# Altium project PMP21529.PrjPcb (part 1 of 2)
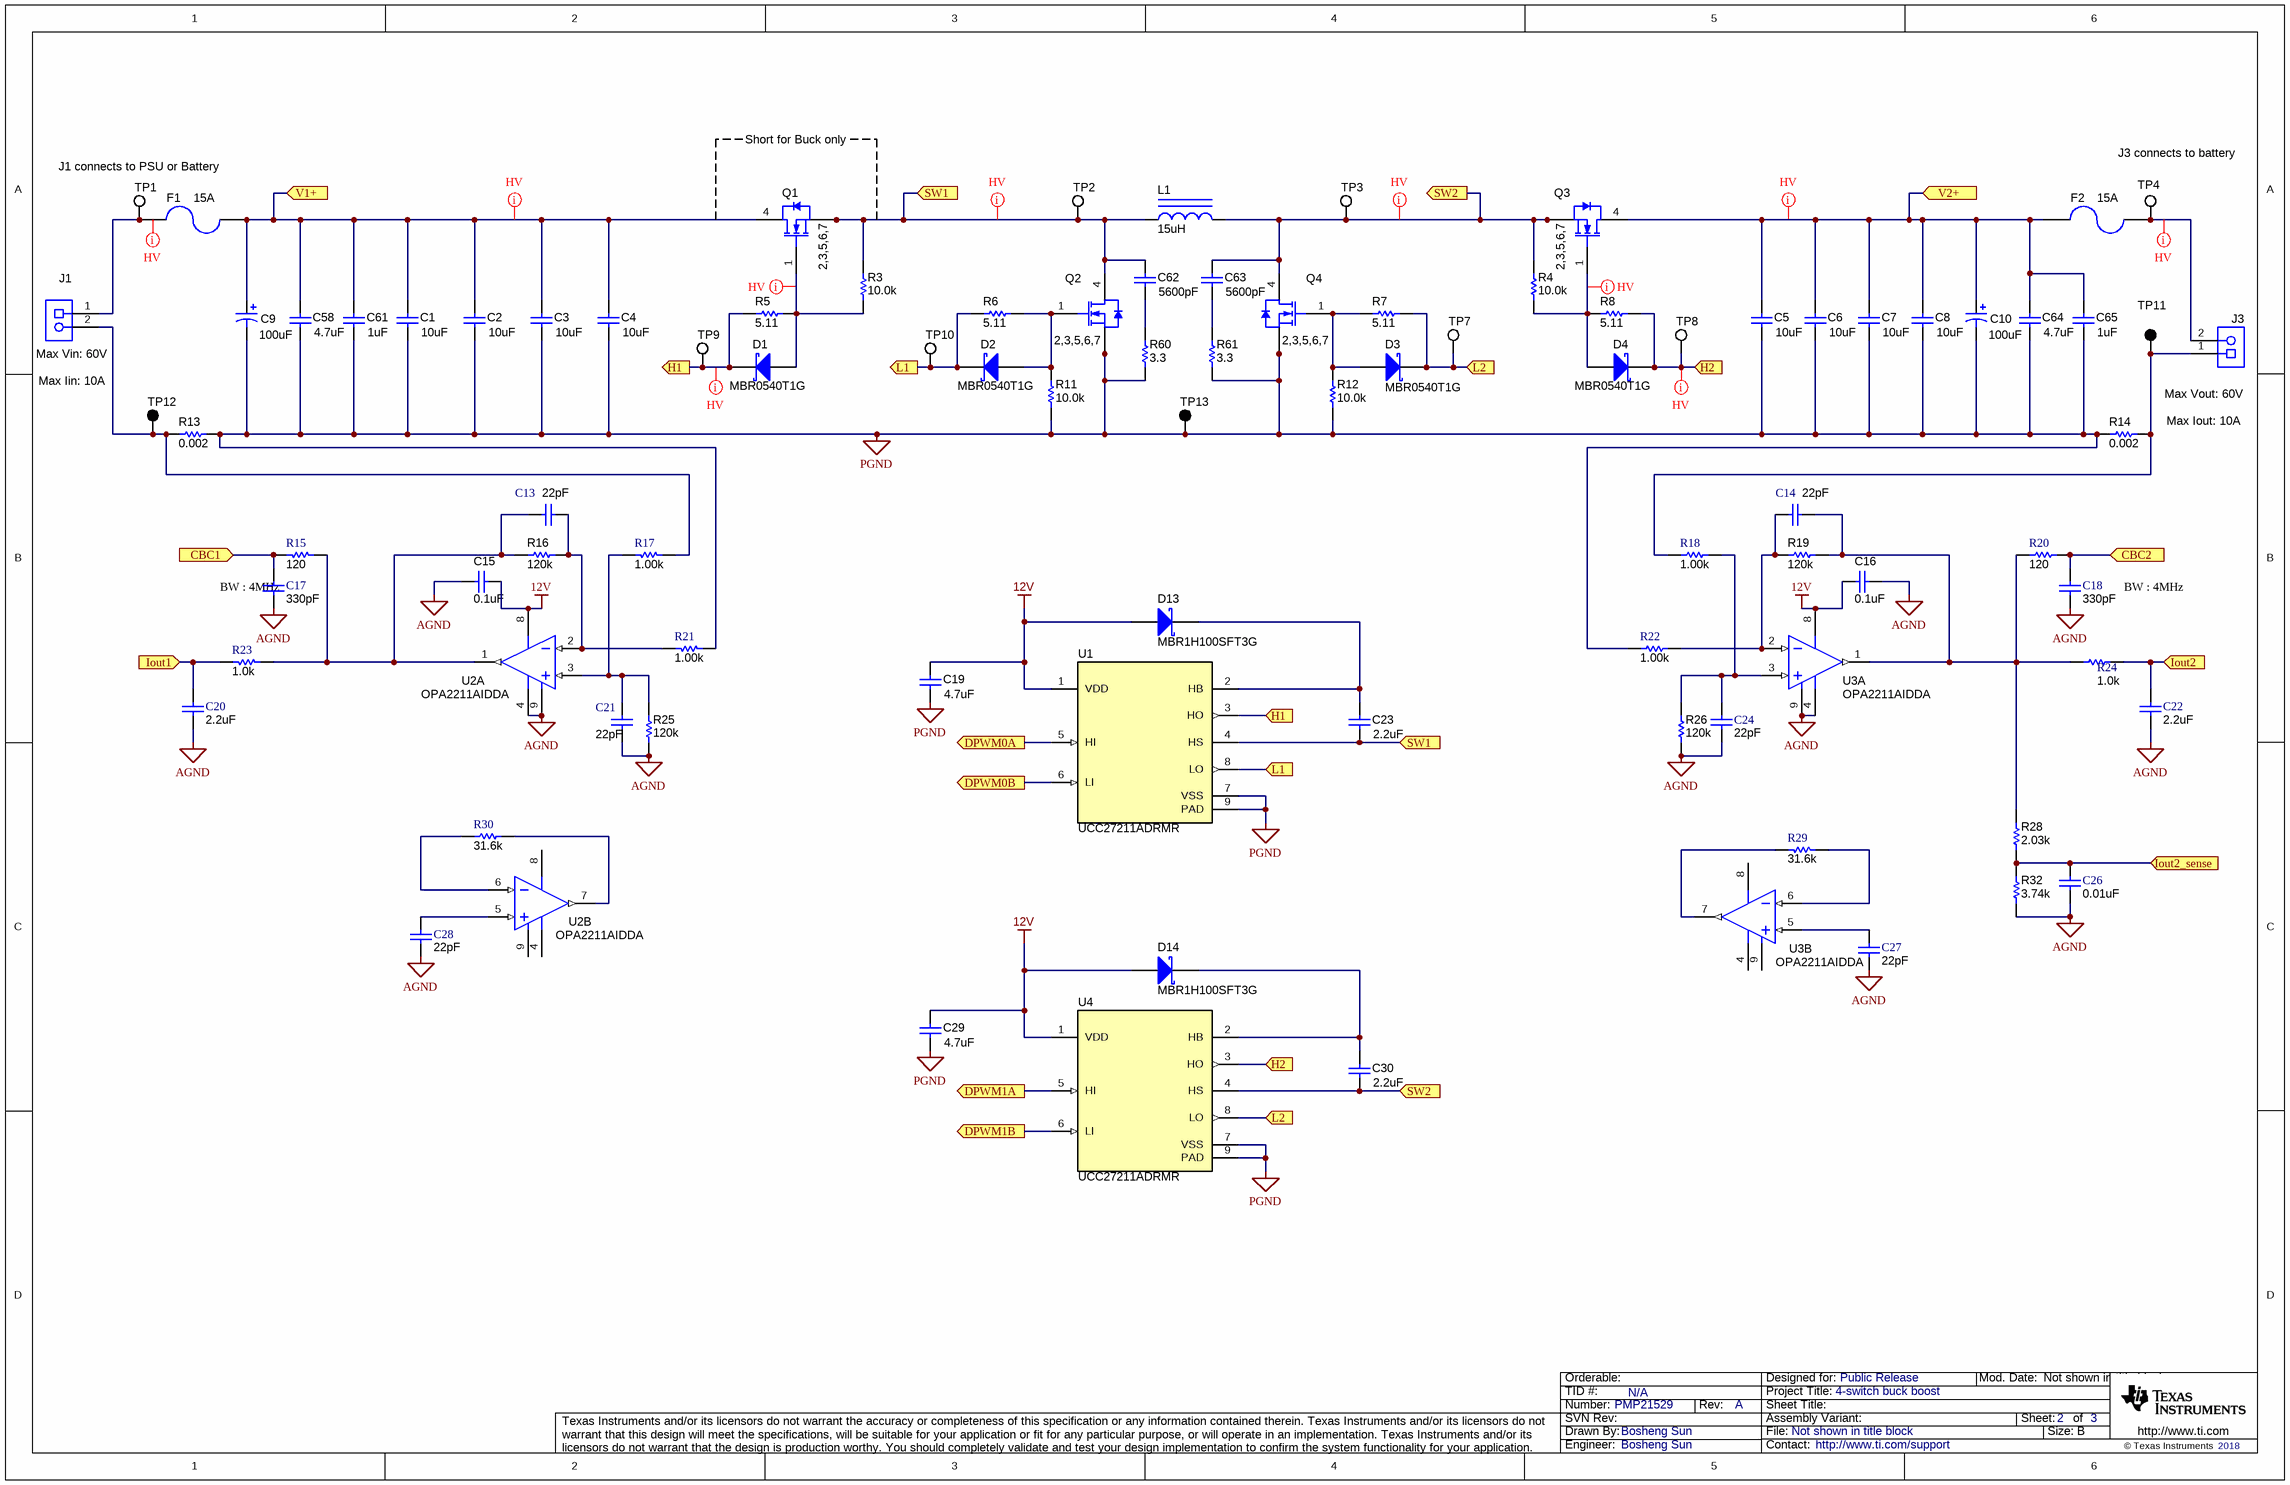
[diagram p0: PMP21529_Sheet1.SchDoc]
CopyrightYear: 2018; PCB_Layout: Bosheng Sun; PCB_Rev: A; PRJ_Customer: Public Release; PRJ_Engineer: Bosheng Sun; PRJ_Number: PMP21529; PRJ_Title: 4-switch buck boost; SCH_Rev: A; TechSupport: http://www.ti.com/support; TID: N/A
3 sheets, 197 parts. Net scope: flat (ports and power ports of the same name join across sheets).
Board file: PMP21529.PcbDoc
Sheets:
  PMP21529_Sheet1.SchDoc
  PMP21529_Sheet2.SchDoc
  PMP21529_Hardware.SchDoc

## Sheet PMP21529_Sheet1.SchDoc
size 431 x 279 mm; Date: Not shown in title block; ApprovedBy: Not shown in title block; CheckedBy: Not shown in title block; Author: Not shown in title block; CompanyName: Not shown in title block; DrawnBy: Bosheng Sun; Engineer: Not shown in title block; Organization: Not shown in title block; Address1: Not shown in title block; Address2: Not shown in title block; Address3: Not shown in title block; Address4: Not shown in title block; DocumentNumber: 1; Revision: Use project parameter SCH_Rev; SheetNumber: 2; SheetTotal: 3; PageSetup: Record=PageOptions¦CenterHorizontal=True¦CenterVertical=True¦PrintScale=1.00¦XCorrection=1.00¦YCorrection=1.00¦PrintKind=0¦BorderSize=5000000¦LeftOffset=0¦BottomOffset=0¦Orientation=2¦PaperLength=1000¦PaperWidth=1000¦Scale=100¦PaperSource=15¦PrintQuality=600¦MediaType=1¦DitherType=10¦PaperKind=Letter¦PrintScaleMode=1

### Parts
C1  ValueDisplayed: 10uF  [2220_280]  (hidden comment: 22201C106MAT2A)
C2  ValueDisplayed: 10uF  [2220_280]  (hidden comment: 22201C106MAT2A)
C3  ValueDisplayed: 10uF  [2220_280]  (hidden comment: 22201C106MAT2A)
C4  ValueDisplayed: 10uF  [2220_280]  (hidden comment: 22201C106MAT2A)
C5  ValueDisplayed: 10uF  [2220_280]  (hidden comment: 22201C106MAT2A)
C6  ValueDisplayed: 10uF  [2220_280]  (hidden comment: 22201C106MAT2A)
C7  ValueDisplayed: 10uF  [2220_280]  (hidden comment: 22201C106MAT2A)
C8  ValueDisplayed: 10uF  [2220_280]  (hidden comment: 22201C106MAT2A)
C9  ValueDisplayed: 100uF  [CAPSMT_62_KE0]  (hidden comment: EMVA101ATR101MKE0S)
C10  ValueDisplayed: 100uF  [CAPSMT_62_KE0]  (hidden comment: EMVA101ATR101MKE0S)
C13  ValueDisplayed: 22pF  [0603]  (hidden comment: Capacitor)
C14  ValueDisplayed: 22pF  [0603]  (hidden comment: Capacitor)
C15  ValueDisplayed: 0.1uF  [0603]  (hidden comment: Capacitor)
C16  ValueDisplayed: 0.1uF  [0603]  (hidden comment: Capacitor)
C17  ValueDisplayed: 330pF  [0603]  (hidden comment: Capacitor)
C18  ValueDisplayed: 330pF  [0603]  (hidden comment: Capacitor)
C19  ValueDisplayed: 4.7uF  [0805_HV]  (hidden comment: GRM21BR71C475KA73L)
C20  ValueDisplayed: 2.2uF  [0603]  (hidden comment: Capacitor)
C21  ValueDisplayed: 22pF  [0603]  (hidden comment: Capacitor)
C22  ValueDisplayed: 2.2uF  [0603]  (hidden comment: Capacitor)
C23  ValueDisplayed: 2.2uF  [1206_180]  (hidden comment: C3216X7S2A225K160AB)
C24  ValueDisplayed: 22pF  [0603]  (hidden comment: Capacitor)
C26  ValueDisplayed: 0.01uF  [0603]  (hidden comment: Capacitor)
C27  ValueDisplayed: 22pF  [0603]  (hidden comment: Capacitor)
C28  ValueDisplayed: 22pF  [0603]  (hidden comment: Capacitor)
C29  ValueDisplayed: 4.7uF  [0805_HV]  (hidden comment: GRM21BR71C475KA73L)
C30  ValueDisplayed: 2.2uF  [1206_180]  (hidden comment: C3216X7S2A225K160AB)
C58  ValueDisplayed: 4.7uF  [1210_220]  (hidden comment: GRM32DC72A475KE01L)
C61  ValueDisplayed: 1uF  [1206_180]  (hidden comment: C3216X7R2A105K160AA)
C62  ValueDisplayed: 5600pF  [1206]  (hidden comment: GRM3195C2A562JA01D)
C63  ValueDisplayed: 5600pF  [1206]  (hidden comment: GRM3195C2A562JA01D)
C64  ValueDisplayed: 4.7uF  [1210_220]  (hidden comment: GRM32DC72A475KE01L)
C65  ValueDisplayed: 1uF  [1206_180]  (hidden comment: C3216X7R2A105K160AA)
D1  MBR0540T1G  [SOD-123]
D2  MBR0540T1G  [SOD-123]
D3  MBR0540T1G  [SOD-123]
D4  MBR0540T1G  [SOD-123]
D13  MBR1H100SFT3G  [SOD-123FL]
D14  MBR1H100SFT3G  [SOD-123FL]
F1  Irating_A: 15A  [FUSE_SSQ]  (hidden comment: SSQ 15)
F2  Irating_A: 15A  [FUSE_SSQ]  (hidden comment: SSQ 15)
J1  Receptacle_2x1  [On-Shore_ED120_2DS]  (value not drawn)
J3  Receptacle_2x1  [On-Shore_ED120_2DS]  (value not drawn)
L1  ValueDisplayed: 15uH  [SER2918H]  (hidden comment: SER2918H-153KL)
Q1  IPB180N08S402ATMA1  [DDPAK-7]  (value not drawn)
Q2  IPB180N08S402ATMA1  [DDPAK-7]  (value not drawn)
Q3  IPB180N08S402ATMA1  [DDPAK-7]  (value not drawn)
Q4  IPB180N08S402ATMA1  [DDPAK-7]  (value not drawn)
R3  ValueDisplayed: 10.0k  [0603]  (hidden comment: CRCW060310K0FKEA)
R4  ValueDisplayed: 10.0k  [0603]  (hidden comment: CRCW060310K0FKEA)
R5  ValueDisplayed: 5.11  [0805_HV]  (hidden comment: CRCW08055R11FKEA)
R6  ValueDisplayed: 5.11  [0805_HV]  (hidden comment: CRCW08055R11FKEA)
R7  ValueDisplayed: 5.11  [0805_HV]  (hidden comment: CRCW08055R11FKEA)
R8  ValueDisplayed: 5.11  [0805_HV]  (hidden comment: CRCW08055R11FKEA)
R11  ValueDisplayed: 10.0k  [0603]  (hidden comment: CRCW060310K0FKEA)
R12  ValueDisplayed: 10.0k  [0603]  (hidden comment: CRCW060310K0FKEA)
R13  ValueDisplayed: 0.002  [2512]  (hidden comment: Resistor)
R14  ValueDisplayed: 0.002  [2512]  (hidden comment: Resistor)
R15  ValueDisplayed: 120  [0603]  (hidden comment: Resistor)
R16  ValueDisplayed: 120k  [0603]  (hidden comment: RC0603FR-07120KL)
R17  ValueDisplayed: 1.00k  [0603]  (hidden comment: Resistor)
R18  ValueDisplayed: 1.00k  [0603]  (hidden comment: Resistor)
R19  ValueDisplayed: 120k  [0603]  (hidden comment: RC0603FR-07120KL)
R20  ValueDisplayed: 120  [0603]  (hidden comment: Resistor)
R21  ValueDisplayed: 1.00k  [0603]  (hidden comment: Resistor)
R22  ValueDisplayed: 1.00k  [0603]  (hidden comment: Resistor)
R23  value 1.0k  [0603]  (hidden comment: Resistor)
R24  value 1.0k  [0603]  (hidden comment: Resistor)
R25  ValueDisplayed: 120k  [0603]  (hidden comment: RC0603FR-07120KL)
R26  ValueDisplayed: 120k  [0603]  (hidden comment: RC0603FR-07120KL)
R28  ValueDisplayed: 2.03k  [0603]  (hidden comment: RT0603DRE072K03L)
R29  value 31.6k  [0603]  (hidden comment: Resistor)
R30  value 31.6k  [0603]  (hidden comment: Resistor)
R32  ValueDisplayed: 3.74k  [0603]  (hidden comment: RC0603FR-073K74L)
R60  ValueDisplayed: 3.3  [2010]  (hidden comment: CRM2010-JW-3R3ELF)
R61  ValueDisplayed: 3.3  [2010]  (hidden comment: CRM2010-JW-3R3ELF)
TP1  5012  [Keystone5012]  (value not drawn)
TP2  5012  [Keystone5012]  (value not drawn)
TP3  5012  [Keystone5012]  (value not drawn)
TP4  5012  [Keystone5012]  (value not drawn)
TP7  5012  [Keystone5012]  (value not drawn)
TP8  5012  [Keystone5012]  (value not drawn)
TP9  5012  [Keystone5012]  (value not drawn)
TP10  5012  [Keystone5012]  (value not drawn)
TP11  5011  [Keystone5011]  (value not drawn)
TP12  5011  [Keystone5011]  (value not drawn)
TP13  5011  [Keystone5011]  (value not drawn)
U1  UCC27211ADRMR  [DRM0008A]
U2  OPA2211AIDDA  [DDA0008C_M]  (parts A,B of 2)
U3  OPA2211AIDDA  [DDA0008C_M]  (parts A,B of 2)
U4  UCC27211ADRMR  [DRM0008A]

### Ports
CBC1, CBC2, DPWM0A, DPWM0B, DPWM1A, DPWM1B, H1, H2, Iout1, Iout2, Iout2_sense, L1, L2, SW1, SW2, V1+, V2+

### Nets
12V: C15.1 C16.1 C19.1 C29.1 D13.2(A) D14.2(A) U1.1(VDD) U2.8(V+) U3.8(V+) U4.1(VDD)
AGND: C15.2 C16.2 C17.2 C18.2 C20.2 C21.2 C22.2 C24.2 C26.2 C27.2 C28.2 R25.1 R26.1 R32.1 U2.4(V-) U2.9(EP) U3.4(V-) U3.9(EP)
PGND: C1.2 C2.2 C3.2 C4.2 C5.2 C6.2 C7.2 C8.2 C9.2(-) C10.2(-) C19.2 C29.2 C58.2 C61.2 C64.2 C65.2 Q2.2(S) Q2.3(S) Q2.5(S) Q2.6(S) Q2.7(S) Q4.2(S) Q4.3(S) Q4.5(S) Q4.6(S) Q4.7(S) R11.1 R12.1 R13.2 R14.1 R21.1 R22.1 R60.1 R61.1 TP13.1 U1.7(VSS) U1.9(PAD) U4.7(VSS) U4.9(PAD)
CBC1: C17.1 R15.2 ; port CBC1
CBC2: C18.1 R20.2 ; port CBC2
DPWM0A: U1.5(HI) ; port DPWM0A
DPWM0B: U1.6(LI) ; port DPWM0B
DPWM1A: U4.5(HI) ; port DPWM1A
DPWM1B: U4.6(LI) ; port DPWM1B
H1: D1.1(K) R5.1 TP9.1 U1.3(HO) ; port H1
H2: D4.1(K) R8.2 TP8.1 U4.3(HO) ; port H2
Iout1: C20.1 R23.2 ; port Iout1
Iout2: C22.1 R24.2 ; port Iout2
Iout2_sense: C26.1 R28.1 R32.2 ; port Iout2_sense
L1: D2.1(K) R6.1 TP10.1 U1.8(LO) ; port L1
L2: D3.1(K) R7.2 TP7.1 U4.8(LO) ; port L2
SW1: C23.2 C62.1 L1.1 Q1.2(S) Q1.3(S) Q1.5(S) Q1.6(S) Q1.7(S) Q2.4(D) R3.2 TP2.1 U1.4(HS) ; port SW1
SW2: C30.2 C63.1 L1.2 Q3.2(S) Q3.3(S) Q3.5(S) Q3.6(S) Q3.7(S) Q4.4(D) R4.2 TP3.1 U4.4(HS) ; port SW2
V1+: C1.1 C2.1 C3.1 C4.1 C9.1(+) C58.1 C61.1 F1.1 Q1.4(D) ; port V1+
V2+: C5.1 C6.1 C7.1 C8.1 C10.1(+) C64.1 C65.1 F2.2 Q3.4(D) ; port V2+
NetC13_1: C13.1 R16.2 R21.2 U2.2(IN_A-)
NetC13_2: C13.2 R15.1 R16.1 R23.1 U2.1(OUT_A)
NetC14_1: C14.1 R19.1 R22.2 U3.2(IN_A-)
NetC14_2: C14.2 R19.2 R20.1 R24.1 R28.2 U3.1(OUT_A)
NetC21_1: C21.1 R17.2 R25.2 U2.3(IN_A+)
NetC23_1: C23.1 D13.1(K) U1.2(HB)
NetC24_1: C24.1 R18.2 R26.2 U3.3(IN_A+)
NetC27_1: C27.1 U3.5(IN_B+)
NetC28_1: C28.1 U2.5(IN_B+)
NetC30_1: C30.1 D14.1(K) U4.2(HB)
NetC62_2: C62.2 R60.2
NetC63_2: C63.2 R61.2
NetD1_2: D1.2(A) Q1.1(G) R3.1 R5.2
NetD2_2: D2.2(A) Q2.1(G) R6.2 R11.2
NetD3_2: D3.2(A) Q4.1(G) R7.1 R12.2
NetD4_2: D4.2(A) Q3.1(G) R4.1 R8.1
NetF1_2: F1.2 J1.1 TP1.1
NetF2_1: F2.1 J3.2 TP4.1
NetJ1_2: J1.2 R13.1 R17.1 TP12.1
NetJ3_1: J3.1 R14.2 R18.1 TP11.1
NetR29_1: R29.1 U3.6(IN_B-)
NetR29_2: R29.2 U3.7(OUT_B)
NetR30_1: R30.1 U2.6(IN_B-)
NetR30_2: R30.2 U2.7(OUT_B)

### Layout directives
net class HV: (no net found under the mark), H1, H2, NetD1_2, NetD4_2, NetF2_1, SW1, SW2, V1+, V2+

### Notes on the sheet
- J1 connects to PSU or Battery
- Short for Buck only
- J3 connects to battery
- (near J1) Max Vin: 60V
- Max Iin: 10A
- Max Vout: 60V
- (near R14) Max Iout: 10A
- BW : 4MHz

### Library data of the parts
C1-C4 C6-C8 = CMP-0009304-2: CAP, CERM, 10 uF, 100 V, +/- 20%, X7R, 2220; Manufacturer: AVX; TaMin_C: -55°C; Polarized: N; SizeAreaWB_mm2: 53.9; Value1: Unknown; U/M: EA; Value: 10uF; TaMax_C: 125°C; SizeZ_mm: 2.8; SizeX_mm: 5.7; SizeY_mm: 5; Cap_Case: 2220; Value2: 100V; SizeArea_mm2: 28.5; Cap_F: 10µF; AEC Category: Q200
C5 = CMP-0009304-2: CAP, CERM, 10 uF, 100 V, +/- 20%, X7R, 2220; Manufacturer: AVX; TaMin_C: -55°C; Polarized: N; SizeAreaWB_mm2: 53.9; Value1: Unknown; U/M: EA; Value: 10uF; TaMax_C: 125°C; SizeZ_mm: 2.8; SizeX_mm: 5.7; SizeY_mm: 5; Cap_Case: 2220; Value2: 100V; SizeArea_mm2: 28.5; CompType: Capacitor; Cap_F: 10µF; AEC Category: Q200
C9 C10 = CMP-0011230-3: CAP, AL, 100 uF, 100 V, +/- 20%, SMD; Manufacturer: Chemi-Con; TaMin_C: -40°C; Polarized: Y; SizeAreaWB_mm2: 225; Value1: Unknown; U/M: EA; Value: 100uF; TaMax_C: 85°C; SizeZ_mm: 13.5; SizeX_mm: 13; Cap_Case: KE0; Value2: 100V; SizeArea_mm2: 169; CompType: Capacitor; Cap_F: 100µF; IRMS_A: 4.4dA; AEC Category: Q200
C13 C14 C21 C24 C27 C28 = CMP-0006775-4: CAP, CERM, 22 pF, 50 V, +/- 5%, C0G/NP0, 0603; PartNumber: 06035A220JAT2A; Manufacturer: AVX; Polarized: N; Value: 22pF; U/M: EA; ESR_ohm: 2.59d; Value1: 0.259 ohm; VDC_V: 50V; TaMin_C: -55°C; TaMax_C: 125°C; AEC Category: Q200; SizeArea_mm2: 1.28; SizeAreaWB_mm2: 4.68; SizeX_mm: 1.6; SizeY_mm: 0.8; SizeZ_mm: 1
C15 C16 = CMP-0006752-5: CAP, CERM, 0.1 uF, 25 V, +/- 5%, X7R, 0603; PartNumber: 06033C104JAT2A; Manufacturer: AVX; Polarized: N; Value: 0.1uF; U/M: EA; Cap_F: 100nF; ESR_ohm: 0.05; Value1: 0.05 ohm; VDC_V: 25V; TaMin_C: -55°C; TaMax_C: 125°C; AEC Category: Q200; SizeArea_mm2: 1.28; SizeAreaWB_mm2: 4.68; SizeX_mm: 1.6; SizeY_mm: 0.8; SizeZ_mm: 1
C17 C18 = CMP-0006784-4: CAP, CERM, 330 pF, 50 V, +/- 5%, C0G/NP0, 0603; PartNumber: 06035A331JAT2A; Manufacturer: AVX; Polarized: N; Value: 330pF; U/M: EA; ESR_ohm: 0.071; Value1: 0.071 ohm; VDC_V: 50V; TaMin_C: -55°C; TaMax_C: 125°C; AEC Category: Q200; SizeArea_mm2: 1.28; SizeAreaWB_mm2: 4.68; SizeX_mm: 1.6; SizeY_mm: 0.8; SizeZ_mm: 1
C19 C29 = CMP-0008334-2: CAP, CERM, 4.7 uF, 16 V, +/- 10%, X7R, 0805; Manufacturer: MuRata; TaMin_C: -55°C; ESR_ohm: 6m; Polarized: N; SizeAreaWB_mm2: 6.75; Value1: 0.006 ohm; U/M: EA; Value: 4.7uF; TaMax_C: 125°C; SizeZ_mm: 1.45; SizeX_mm: 2; SizeY_mm: 1.25; Cap_Case: 0805; Value2: 16V; SizeArea_mm2: 2.5; CompType: Capacitor; Cap_F: 4.7µF; AEC Category: Q200
C20 C22 = CMP-0006906-5: CAP, CERM, 2.2 uF, 10 V, +/- 10%, X5R, 0603; PartNumber: C0603C225K8PACTU; Manufacturer: Kemet; Polarized: N; Value: 2.2uF; U/M: EA; Cap_F: 2.2µF; Value1: Unknown; VDC_V: 10V; TaMin_C: -55°C; TaMax_C: 85°C; AEC Category: Q200; SizeArea_mm2: 1.28; SizeAreaWB_mm2: 4.68; SizeX_mm: 1.6; SizeY_mm: 0.8; SizeZ_mm: 1
C23 C30 = CMP-0008724-2: CAP, CERM, 2.2 uF, 100 V, +/- 10%, X7S, 1206; Manufacturer: TDK; TaMin_C: -55°C; ESR_ohm: 5.718m; Polarized: N; SizeAreaWB_mm2: 10.92; Value1: 0.005718 ohm; U/M: EA; Value: 2.2uF; TaMax_C: 125°C; SizeZ_mm: 1.8; SizeX_mm: 3.2; SizeY_mm: 1.6; Value2: 100V; SizeArea_mm2: 5.12; Cap_F: 2.2µF; IRMS_A: 3.03632A; AEC Category: Q200
C26 = CMP-0006726-4: CAP, CERM, 0.01 uF, 100 V, +/- 5%, X7R, 0603; PartNumber: 06031C103JAT2A; Manufacturer: AVX; Polarized: N; Value: 0.01uF; U/M: EA; Cap_F: 10nF; ESR_ohm: 0.098; Value1: 0.098 ohm; VDC_V: 100V; TaMin_C: -55°C; TaMax_C: 125°C; AEC Category: Q200; SizeArea_mm2: 1.28; SizeAreaWB_mm2: 4.68; SizeX_mm: 1.6; SizeY_mm: 0.8; SizeZ_mm: 1
C58 = CMP-0009182-2: CAP, CERM, 4.7 uF, 100 V, +/- 10%, X7S, 1210; Manufacturer: MuRata; TaMin_C: -55°C; Polarized: N; SizeAreaWB_mm2: 14.7; Value1: Unknown; U/M: EA; Value: 4.7uF; TaMax_C: 125°C; SizeZ_mm: 2.2; SizeX_mm: 3.2; SizeY_mm: 2.5; Cap_Case: 1210; Value2: 100V; SizeArea_mm2: 8; Cap_F: 4.7µF; AEC Category: Q200
C61 = CMP-0008710-2: CAP, CERM, 1 uF, 100 V, +/- 10%, X7R, 1206; Manufacturer: TDK; TaMin_C: -55°C; ESR_ohm: 4.575m; Polarized: N; SizeAreaWB_mm2: 10.92; Value1: 0.004575 ohm; U/M: EA; Value: 1uF; TaMax_C: 125°C; SizeZ_mm: 1.8; SizeX_mm: 3.2; SizeY_mm: 1.6; Value2: 100V; SizeArea_mm2: 5.12; Cap_F: 1µF; IRMS_A: 3.39639A; AEC Category: Q200
C62 C63 = CMP-0008852-2: CAP, CERM, 5600 pF, 100 V, +/- 5%, C0G/NP0, 1206; Manufacturer: MuRata; TaMin_C: -55°C; ESR_ohm: 5m; Polarized: N; SizeAreaWB_mm2: 10.92; Value1: 0.005 ohm; U/M: EA; Value: 5600pF; TaMax_C: 125°C; SizeZ_mm: 1.35; SizeX_mm: 3.2; SizeY_mm: 1.6; Value2: 100V; SizeArea_mm2: 5.12; Cap_F: 5.6nF; IRMS_A: 5dA; AEC Category: Q200
C64 = CMP-0009182-2: CAP, CERM, 4.7 uF, 100 V, +/- 10%, X7S, 1210; Manufacturer: MuRata; TaMin_C: -55°C; Polarized: N; SizeAreaWB_mm2: 14.7; Value1: Unknown; U/M: EA; Value: 4.7uF; TaMax_C: 125°C; SizeZ_mm: 2.2; SizeX_mm: 3.2; SizeY_mm: 2.5; Cap_Case: 1210; Value2: 100V; SizeArea_mm2: 8; CompType: Capacitor; Cap_F: 4.7µF; AEC Category: Q200
C65 = CMP-0008710-2: CAP, CERM, 1 uF, 100 V, +/- 10%, X7R, 1206; Manufacturer: TDK; TaMin_C: -55°C; ESR_ohm: 4.575m; Polarized: N; SizeAreaWB_mm2: 10.92; Value1: 0.004575 ohm; U/M: EA; Value: 1uF; TaMax_C: 125°C; SizeZ_mm: 1.8; SizeX_mm: 3.2; SizeY_mm: 1.6; Value2: 100V; SizeArea_mm2: 5.12; CompType: Capacitor; Cap_F: 1µF; IRMS_A: 3.39639A; AEC Category: Q200
D1-D4 = CMP-0028526-1: Diode, Schottky, 40 V, 0.5 A, SOD-123; Manufacturer: ON Semiconductor; Io_A: 5dA; Green_Lifecycle: Active; SizeAreaWB_mm2: 13.095; Vr_V: 40V; Green_REACh: Passed; Value1: 0.5A; TJmax_C: 150°C; U/M: EA; Value: 40V; SizeZ_mm: 1.35; SizeX_mm: 3.85; SizeY_mm: 1.7; Vf_V: 5.1dV; Value2: 0.51V; SizeArea_mm2: 6.545; AEC Category: Q101; RJC_CperW: 118
D13 D14 = CMP-0028625-1: Diode, Schottky, 100 V, 1 A, SOD-123FL; Manufacturer: ON Semiconductor; Io_A: 1A; Green_Lifecycle: Active; SizeAreaWB_mm2: 12.19; Vr_V: 100V; Green_REACh: Passed; TJmax_C: 175°C; U/M: EA; Value: 100V; SizeZ_mm: 0.98; SizeX_mm: 3.6; SizeY_mm: 1.65; Vf_V: 7.6dV; Value2: 0.76V; SizeArea_mm2: 5.94; AEC Category: Q101; RJC_CperW: 85
F1 F2 = CMP-0003604-2: Fuse, 15 A, SMD; Manufacturer: Bel Fuse; Rtyp_Ohm: 4m
J1 J3 = CMP-0074910-1: Terminal Block, 5.08 mm, 2x1, Brass, TH; PartNumber: ED120/2DS; Manufacturer: On-Shore Technology; Pitch_mm: 5.08; Gender: Female; Shrouded: N; Row_Count: 1; Current_A: 15A; Voltage_V: 300V; Cert_CULUS: Y; CNHeader: False; CT: True; Green_Lifecycle: Not Set; Green_REACh: Incomplete
L1 = CMP-0061637-2: Inductor, Shielded E Core, Ferrite, 15 uH, 21.9 A, 0.0026 ohm, SMD; Manufacturer: Coilcraft; Isat: 21.9A @ 30% inductance drop; Irms: 28A @ 40C rise; Green_Lifecycle: Not Set; SizeAreaWB_mm2: 651.82; DCR_ohm: 2.6m; Green_REACh: Incomplete; Value: 15uH; Imax_A: 21.9A; SizeZ_mm: 17.78; SizeX_mm: 27.9; SizeY_mm: 19.8; SizeArea_mm2: 552.42; Ind_H: 15µH; AEC Category: Q200
Q1-Q4 = CMP-0000920-1: MOSFET, N-CH, 80 V, 180 A, AEC-Q101, DDPAK-7; Alternate Manufacturer: None; Manufacturer: Infineon Technologies; SizeZ_mm: 4.445; ChType: N; Value2: 128 nC; VdsMax_V: 80V; SizeX_mm: 15.245; SizeAreaWB_mm2: 209.6992; SizeY_mm: 10.16; Vgs_V: 20V; QgTyp_nC: 128; AEC Qualified: Y; Value: 80V; SizeArea_mm2: 154.8892; AEC Category: Q101; IdsMax_A: 180A; U/M: EA
R3 R4 R11 R12 = CMP-0021998-4: RES, 10.0 k, 1%, 0.1 W, AEC-Q200 Grade 0, 0603; Manufacturer: Vishay-Dale; Power_W: 100mW; TempCo: 100 ppm/C; Value_Code: 10k0; Value: 10.0k; EIA_Code: E96; Res_ohm: 10k; SizeX_mm: 1.6; SizeY_mm: 0.8; SizeZ_mm: 1; Value2: 0.1W; SizeArea_mm2: 1.28; AEC Qualified: Y; VDC_V: 75V; AEC Category: Q200; AEC Grade: 0
R5-R8 = CMP-0021358-3: RES, 5.11, 1%, 0.125 W, AEC-Q200 Grade 0, 0805; Manufacturer: Vishay-Dale; Power_W: 125mW; TempCo: 100 ppm/C; Value_Code: 5R11; Value: 5.11; EIA_Code: E96; SizeX_mm: 2; SizeY_mm: 1.25; SizeZ_mm: 1.45; Value2: 0.125W; SizeArea_mm2: 2.5; AEC Qualified: Y; VDC_V: 150V; AEC Category: Q200; AEC Grade: 0
R13 R14 = CMP-0015819-2: RES, 0.002, 1%, 1 W, 2512; PartNumber: ERJ-M1WTF2M0U; Manufacturer: Panasonic; Value: 0.002; Res_ohm: 2m; Value_Code: 2L000; Power_W: 1W; TempCo: ppm/C; U/M: EA; AEC Category: Q200; SizeArea_mm2: 20.16; SizeX_mm: 6.3; SizeY_mm: 3.2; SizeZ_mm: 0.71
R15 R20 = CMP-0025710-4: RES, 120, 5%, 0.1 W, AEC-Q200 Grade 0, 0603; PartNumber: CRCW0603120RJNEA; Manufacturer: Vishay-Dale; Value: 120; Value_Code: 120R; Power_W: 100mW; Value2: 0.1W; VDC_V: 75V; TempCo: 200 ppm/C; EIA_Code: E24; AEC Category: Q200; AEC Grade: 0; AEC Qualified: Y; SizeArea_mm2: 1.28; SizeX_mm: 1.6; SizeY_mm: 0.8; SizeZ_mm: 1
R16 = CMP-0022768-4: RES, 120 k, 1%, 0.1 W, 0603; Manufacturer: Yageo; Power_W: 100mW; TempCo: 100 ppm/C; Value: 120k; SizeX_mm: 1.6; SizeY_mm: 0.8; SizeZ_mm: 1; Value2: 0.1W; SizeArea_mm2: 1.28; CompType: Resistor; AEC Qualified: N; VDC_V: 75V; AEC Category: Q200; SizeAreaWB_mm2: 4.68
R17 R18 R21 R22 = CMP-0022109-5: RES, 1.00 k, 1%, 0.1 W, AEC-Q200 Grade 0, 0603; PartNumber: CRCW06031K00FKEA; Manufacturer: Vishay-Dale; Value: 1.00k; Res_ohm: 1k; Value_Code: 1k00; Power_W: 100mW; Value2: 0.1W; VDC_V: 75V; TempCo: 100 ppm/C; EIA_Code: E96; SizeArea_mm2: 1.28; SizeX_mm: 1.6; SizeY_mm: 0.8; SizeZ_mm: 1; AEC Category: Q200; AEC Qualified: Y; AEC Grade: 0
R19 R25 R26 = CMP-0022768-4: RES, 120 k, 1%, 0.1 W, 0603; Manufacturer: Yageo; Power_W: 100mW; TempCo: 100 ppm/C; Value: 120k; SizeX_mm: 1.6; SizeY_mm: 0.8; SizeZ_mm: 1; Value2: 0.1W; SizeArea_mm2: 1.28; AEC Qualified: N; VDC_V: 75V; AEC Category: Q200; SizeAreaWB_mm2: 4.68
R23 R24 = CMP-0025729-4: RES, 1.0 k, 5%, 0.1 W, AEC-Q200 Grade 0, 0603; PartNumber: CRCW06031K00JNEA; Manufacturer: Vishay-Dale; Res_ohm: 1k; Value_Code: 1k00; Power_W: 100mW; Value2: 0.1W; VDC_V: 75V; TempCo: 200 ppm/C; EIA_Code: E24; AEC Category: Q200; AEC Grade: 0; AEC Qualified: Y; SizeArea_mm2: 1.28; SizeX_mm: 1.6; SizeY_mm: 0.8; SizeZ_mm: 1
R28 = CMP-0025047-3: RES, 2.03 k, 0.5%, 0.1 W, 0603; Manufacturer: Yageo America; Power_W: 100mW; TempCo: 50 ppm/C; Value_Code: 2k03; U/M: EA; Value: 2.03k; EIA_Code: E192; SizeX_mm: 1.6; SizeY_mm: 0.8; SizeZ_mm: 1; Value2: 0.1W; SizeArea_mm2: 1.28; CompType: Resistor; VDC_V: 75V; AEC Category: Q200
R29 R30 = CMP-0022330-4: RES, 31.6 k, 1%, 0.1 W, AEC-Q200 Grade 0, 0603; PartNumber: CRCW060331K6FKEA; Manufacturer: Vishay-Dale; Value_Code: 31k6; Power_W: 100mW; Value2: 0.1W; VDC_V: 75V; TempCo: 100 ppm/C; EIA_Code: E96; AEC Category: Q200; AEC Grade: 0; AEC Qualified: Y; SizeArea_mm2: 1.28; SizeX_mm: 1.6; SizeY_mm: 0.8; SizeZ_mm: 1
R32 = CMP-0023087-5: RES, 3.74 k, 1%, 0.1 W, 0603; Manufacturer: Yageo; Power_W: 100mW; TempCo: 100 ppm/C; Value_Code: 3k74; Value: 3.74k; EIA_Code: E96; SizeX_mm: 1.6; SizeY_mm: 0.8; SizeZ_mm: 1; Value2: 0.1W; SizeArea_mm2: 1.28; AEC Qualified: N; VDC_V: 75V; AEC Category: Q200; SizeAreaWB_mm2: 4.68
R60 R61 = CMP-0016195-2: RES, 3.3, 5%, 1 W, 2010; Manufacturer: Bourns; Power_W: 1W; TempCo: 100 ppm/C; Value_Code: 3R30; U/M: EA; Value: 3.3; EIA_Code: E24; SizeX_mm: 5; SizeY_mm: 2.5; SizeZ_mm: 1.66; SizeArea_mm2: 12.5; VDC_V: 2V; AEC Category: Q200
TP1-TP4 TP7-TP10 = CMP-0055149-1: Test Point, Multipurpose, White, TH; Manufacturer: Keystone; CNHeader: FALSE; Green_Lifecycle: Active; Green_REACh: Passed; ContactFinish: Silver; CT: TRUE
TP11-TP13 = CMP-0055148-1: Test Point, Multipurpose, Black, TH; Manufacturer: Keystone; CNHeader: FALSE; Green_Lifecycle: Active; Green_REACh: Passed; ContactFinish: Silver; CT: TRUE
U1 U4 = CMP-0066939-1: 120-V Boot, 4-A Peak, High Frequency High-Side and Low-Side Driver, DRM0008A (VSON-8); Alternate PartNumber: UCC27211ADRMT; Alternate Manufacturer: Texas Instruments; SizeAreaWB_mm2: 25.0; U/M: EA; SizeZ_mm: 1.0; SizeX_mm: 4.0; SizeArea_mm2: 16.0; CompType: IC
U2 U3 = CMP-0040615-2: 1.1 nV/rtHz Noise, Low Power, Precision Operational Amplifier, 4.5 to 36 V, -40 to 125 degC, 8-pin SOP (DDA8), Green (RoHS & no Sb/Br); Manufacturer: Texas Instruments; Sub Family: High Supply Voltage Amplifier (>=30V), Low Noise Amp (<=10nV/rtHz), Low Offset Voltage Amplifier (<=500uV), Precision Amplifier; Total Supply Voltage(Min)(+5V is 5, +/-5V is 10): 4.5; Slew Rate(Typ)(V/us): 27; Vio (25C)(Max)(mV): 0.15; Total Supply Voltage(Max)(+5V is 5, +/-5V is 10): 36; IIB(Max)(pA): 175000; GBW(Typ)(MHz): 45; Rating: Catalog; Offset Drift(Typ)(uV/C): 0.35; Packing: TUBE; CMRR(Min)(dB): 114; Number of Channels: 2

## Sheet PMP21529_Sheet2.SchDoc
size 431 x 279 mm; Date: Not shown in title block; ApprovedBy: Not shown in title block; CheckedBy: Not shown in title block; Author: Not shown in title block; CompanyName: Not shown in title block; DrawnBy: Bosheng Sun; Engineer: Not shown in title block; Organization: Not shown in title block; Address1: Not shown in title block; Address2: Not shown in title block; Address3: Not shown in title block; Address4: Not shown in title block; DocumentNumber: 1; Revision: Use project parameter SCH_Rev; SheetNumber: 2; SheetTotal: 3; PageSetup: Record=PageOptions¦CenterHorizontal=True¦CenterVertical=True¦PrintScale=1.00¦XCorrection=1.00¦YCorrection=1.00¦PrintKind=0¦BorderSize=5000000¦LeftOffset=0¦BottomOffset=0¦Orientation=2¦PaperLength=1000¦PaperWidth=1000¦Scale=100¦PaperSource=15¦PrintQuality=600¦MediaType=1¦DitherType=10¦PaperKind=Letter¦PrintScaleMode=1
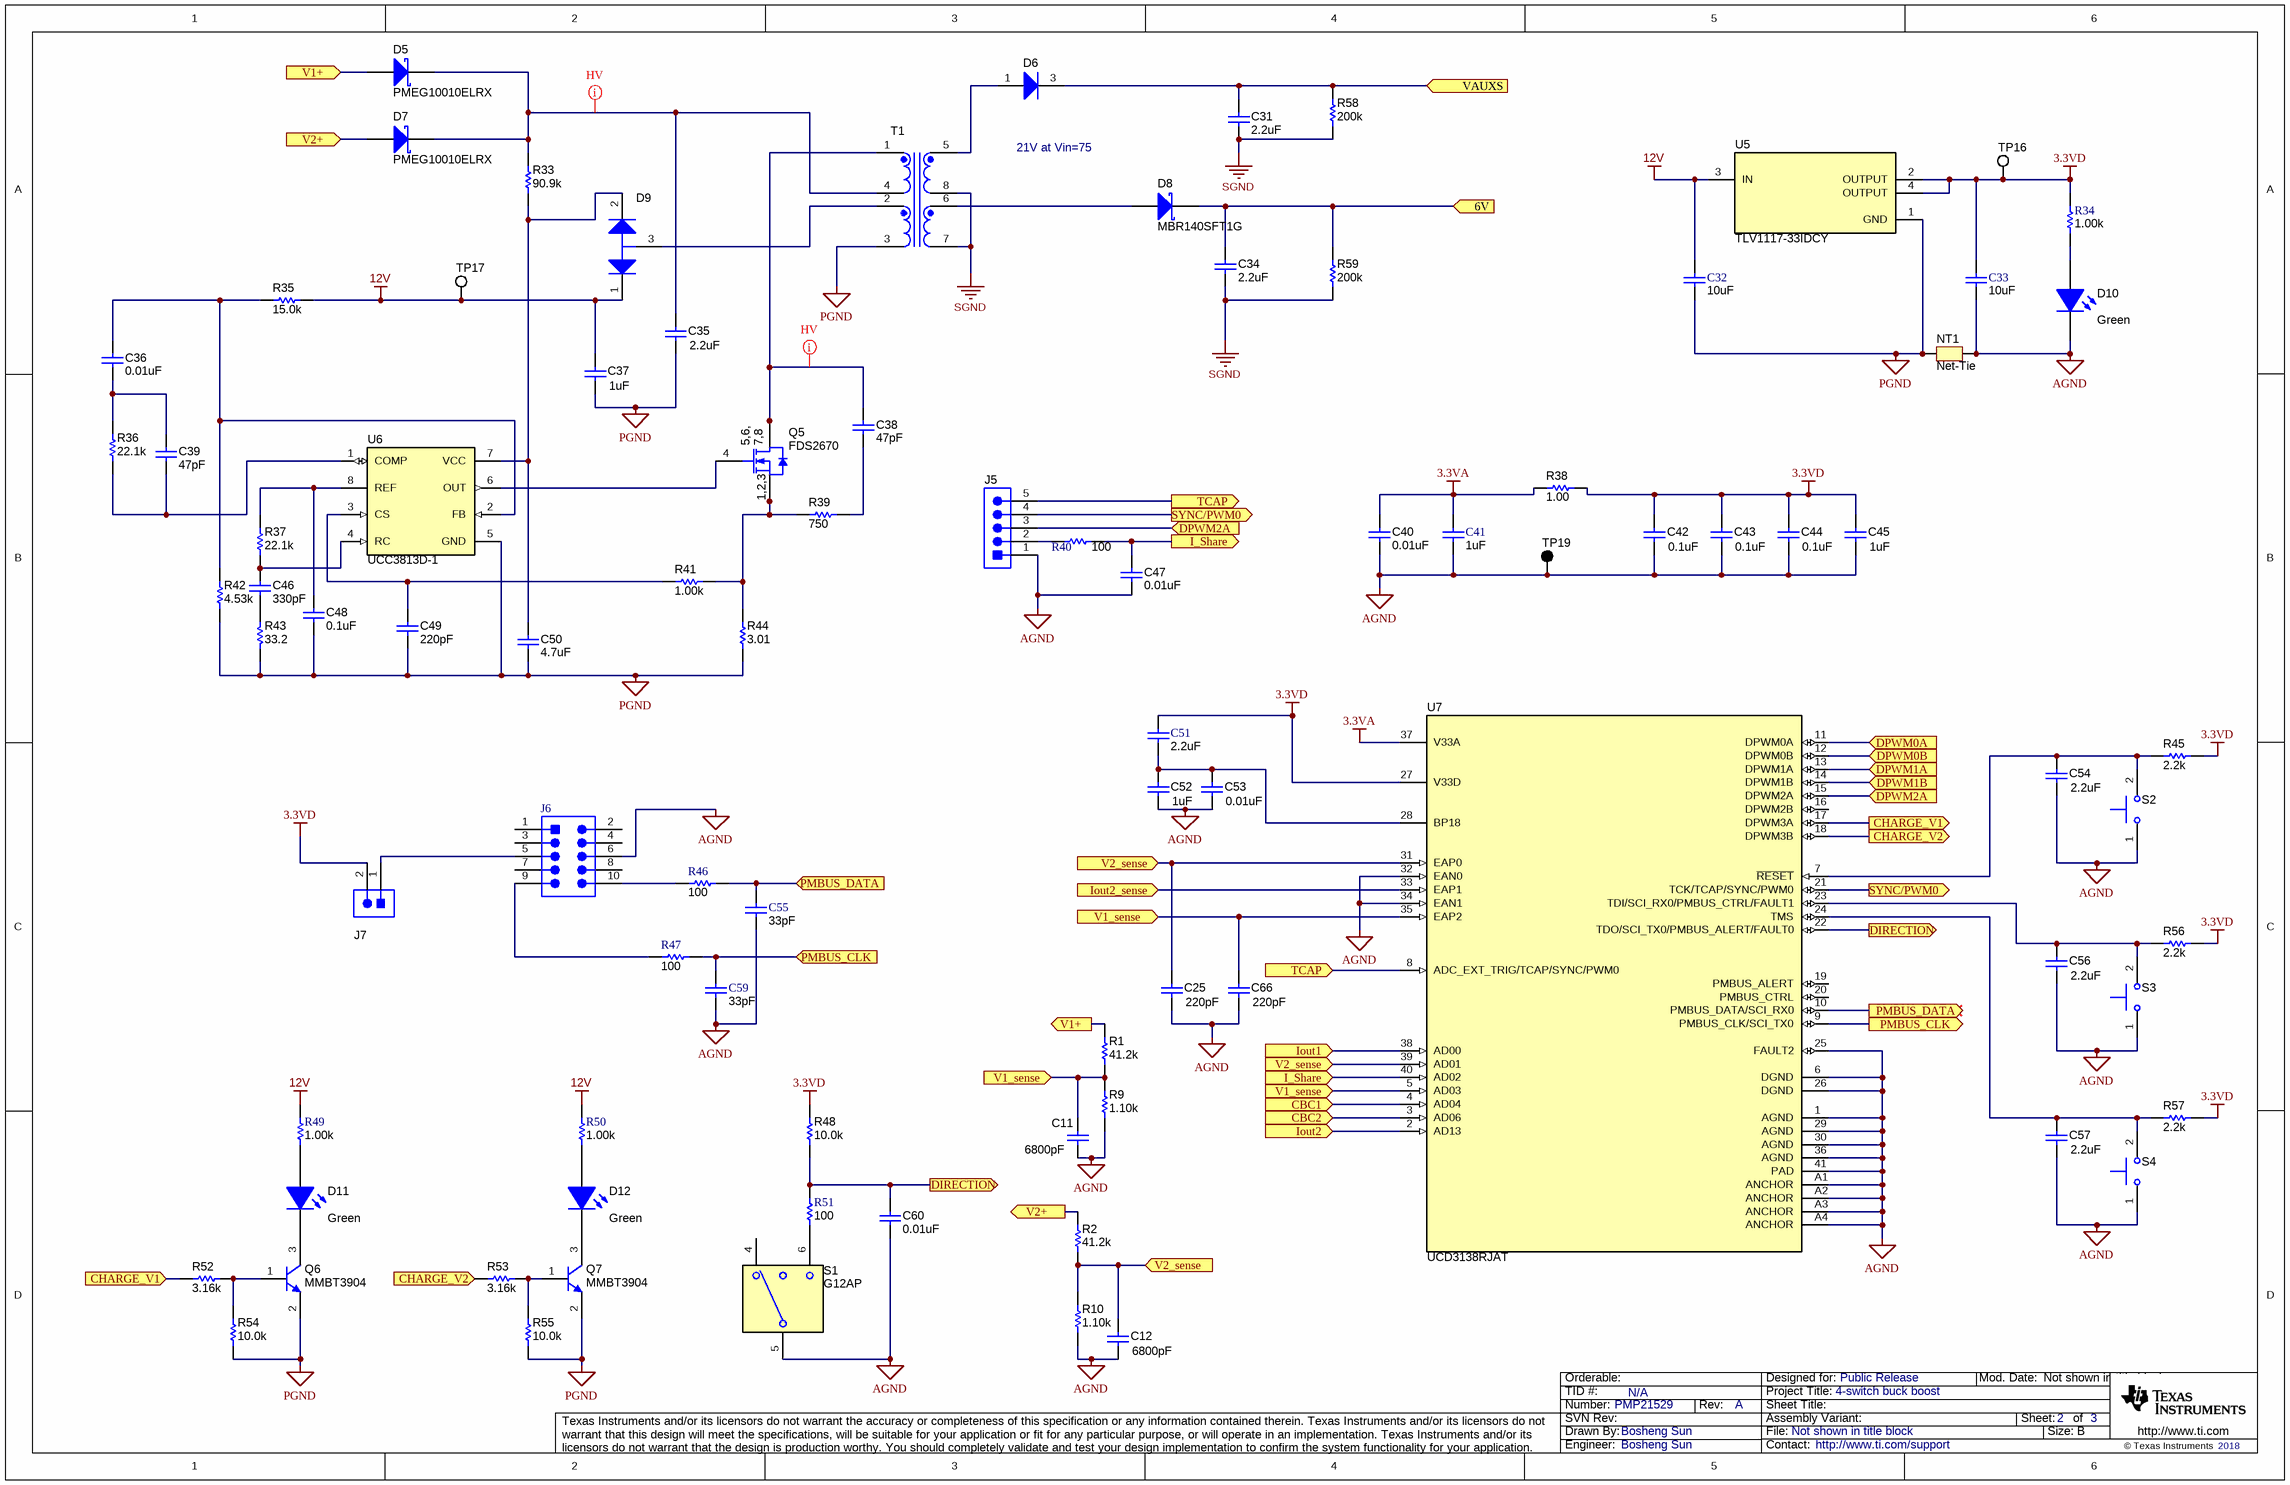
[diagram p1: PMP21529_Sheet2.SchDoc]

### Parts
C11  ValueDisplayed: 6800pF  [0603]  (hidden comment: GRM188R71E682KA01D)
C12  ValueDisplayed: 6800pF  [0603]  (hidden comment: GRM188R71E682KA01D)
C25  ValueDisplayed: 220pF  [0603]  (hidden comment: C0603C221K5RACTU)
C31  ValueDisplayed: 2.2uF  [0805_HV]  (hidden comment: Capacitor)
C32  ValueDisplayed: 10uF  [0805_HV]  (hidden comment: Capacitor)
C33  ValueDisplayed: 10uF  [0603]  (hidden comment: Capacitor)
C34  ValueDisplayed: 2.2uF  [0805_HV]  (hidden comment: Capacitor)
C35  ValueDisplayed: 2.2uF  [1210_270]  (hidden comment: GRM32ER72A225KA35L)
C36  ValueDisplayed: 0.01uF  [0603]  (hidden comment: Capacitor)
C37  ValueDisplayed: 1uF  [0603]  (hidden comment: EMK107B7105KA-T)
C38  ValueDisplayed: 47pF  [0805_HV]  (hidden comment: Capacitor)
C39  ValueDisplayed: 47pF  [0603]  (hidden comment: Capacitor)
C40  ValueDisplayed: 0.01uF  [0603]  (hidden comment: Capacitor)
C41  ValueDisplayed: 1uF  [0603]  (hidden comment: Capacitor)
C42  ValueDisplayed: 0.1uF  [0402]  (hidden comment: GRM155R71E104KE14D)
C43  ValueDisplayed: 0.1uF  [0402]  (hidden comment: GRM155R71E104KE14D)
C44  ValueDisplayed: 0.1uF  [0402]  (hidden comment: GRM155R71E104KE14D)
C45  ValueDisplayed: 1uF  [0402]  (hidden comment: GRM155R70J105KA12D)
C46  ValueDisplayed: 330pF  [0603]  (hidden comment: Capacitor)
C47  ValueDisplayed: 0.01uF  [0603]  (hidden comment: Capacitor)
C48  ValueDisplayed: 0.1uF  [0603]  (hidden comment: Capacitor)
C49  ValueDisplayed: 220pF  [0603]  (hidden comment: Capacitor)
C50  ValueDisplayed: 4.7uF  [0805_HV]  (hidden comment: Capacitor)
C51  ValueDisplayed: 2.2uF  [0603]  (hidden comment: Capacitor)
C52  ValueDisplayed: 1uF  [0603]  (hidden comment: EMK107B7105KA-T)
C53  ValueDisplayed: 0.01uF  [0603]  (hidden comment: C0603H103J3GACTU)
C54  ValueDisplayed: 2.2uF  [0603]  (hidden comment: EMK107BB7225MA-T)
C55  ValueDisplayed: 33pF  [0603]  (hidden comment: Capacitor)
C56  ValueDisplayed: 2.2uF  [0603]  (hidden comment: EMK107BB7225MA-T)
C57  ValueDisplayed: 2.2uF  [0603]  (hidden comment: EMK107BB7225MA-T)
C59  ValueDisplayed: 33pF  [0603]  (hidden comment: Capacitor)
C60  ValueDisplayed: 0.01uF  [0603]  (hidden comment: Capacitor)
C66  ValueDisplayed: 220pF  [0603]  (hidden comment: C0603C221K5RACTU)
D5  PMEG10010ELRX  [SOD-123W]
D6  DIODE_A1C3  [SOT-23L]  (value not drawn)
D7  PMEG10010ELRX  [SOD-123W]
D8  MBR140SFT1G  [SOD-123FL]
D9  DIODE_A3C1_A3C2  [SOT-23L]  (value not drawn)
D10  value Green  [LED_LTST-C190]  (hidden comment: LTST-C190GKT)
D11  value Green  [LED_LTST-C190]  (hidden comment: LTST-C190GKT)
D12  value Green  [LED_LTST-C190]  (hidden comment: LTST-C190GKT)
J5  HTSW-105-07-G-S  [Samtec_HTSW-105-07-G-S]  (value not drawn)
J6  Header_5x2  [CONN_5103308-1]  (value not drawn)
J7  HTSW-102-09-G-S  [Samtec_HTSW-102-09-x-S]  (value not drawn)
NT1  Net-Tie  [Net-Tie_50milWide_30milLong]  (net tie, no BOM)
Q5  FDS2670  [SOIC-8]
Q6  MMBT3904  [SOT-23]
Q7  MMBT3904  [SOT-23]
R1  ValueDisplayed: 41.2k  [0603]  (hidden comment: RT0603BRD0741K2L)
R2  ValueDisplayed: 41.2k  [0603]  (hidden comment: RT0603BRD0741K2L)
R9  ValueDisplayed: 1.10k  [0603]  (hidden comment: RT0603BRD071K1L)
R10  ValueDisplayed: 1.10k  [0603]  (hidden comment: RT0603BRD071K1L)
R33  value 90.9k  [0805_HV]  (hidden comment: Resistor)
R34  value 1.00k  [0603]  (hidden comment: Resistor)
R35  ValueDisplayed: 15.0k  [0603]  (hidden comment: Resistor)
R36  ValueDisplayed: 22.1k  [0603]  (hidden comment: Resistor)
R37  ValueDisplayed: 22.1k  [0603]  (hidden comment: Resistor)
R38  ValueDisplayed: 1.00  [0603]  (hidden comment: RT0603DRE071RL)
R39  ValueDisplayed: 750  [0603]  (hidden comment: Resistor)
R40  value 100  [0603]  (hidden comment: Resistor)
R41  ValueDisplayed: 1.00k  [0603]  (hidden comment: Resistor)
R42  ValueDisplayed: 4.53k  [0603]  (hidden comment: CRCW06034K53FKEA)
R43  ValueDisplayed: 33.2  [0603]  (hidden comment: Resistor)
R44  value 3.01  [0805_HV]  (hidden comment: Resistor)
R45  ValueDisplayed: 2.2k  [0603]  (hidden comment: CRCW06032K20JNEA)
R46  value 100  [0603]  (hidden comment: Resistor)
R47  value 100  [0603]  (hidden comment: Resistor)
R48  ValueDisplayed: 10.0k  [0603]  (hidden comment: CRCW060310K0FKEA)
R49  value 1.00k  [0603]  (hidden comment: Resistor)
R50  value 1.00k  [0603]  (hidden comment: Resistor)
R51  value 100  [0603]  (hidden comment: Resistor)
R52  ValueDisplayed: 3.16k  [0603]  (hidden comment: CRCW06033K16FKEA)
R53  ValueDisplayed: 3.16k  [0603]  (hidden comment: CRCW06033K16FKEA)
R54  ValueDisplayed: 10.0k  [0603]  (hidden comment: CRCW060310K0FKEA)
R55  ValueDisplayed: 10.0k  [0603]  (hidden comment: CRCW060310K0FKEA)
R56  ValueDisplayed: 2.2k  [0603]  (hidden comment: CRCW06032K20JNEA)
R57  ValueDisplayed: 2.2k  [0603]  (hidden comment: CRCW06032K20JNEA)
R58  ValueDisplayed: 200k  [0603]  (hidden comment: CRCW0603200KJNEA)
R59  ValueDisplayed: 200k  [0603]  (hidden comment: CRCW0603200KJNEA)
S1  G12AP  [SW_G1xAP]
S2  SKRKAEE010  [SW_SKRKAEE010]  (value not drawn)
S3  SKRKAEE010  [SW_SKRKAEE010]  (value not drawn)
S4  SKRKAEE010  [SW_SKRKAEE010]  (value not drawn)
T1  XFMR_031-00019  [XFMR_031-00019]  (value not drawn)
TP16  5012  [Keystone5012]  (value not drawn)
TP17  5012  [Keystone5012]  (value not drawn)
TP19  5011  [Keystone5011]  (value not drawn)
U5  TLV1117-33IDCY  [DCY0004A_N]
U6  UCC3813D-1  [D0008A_N]
U7  UCD3138RJAT  [RJA0040A]

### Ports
6V, CBC1, CBC2, CHARGE_V1, CHARGE_V2, DIRECTION, DPWM0A, DPWM0B, DPWM1A, DPWM1B, DPWM2A, I_Share, Iout1, Iout2, Iout2_sense, PMBUS_CLK, PMBUS_DATA, SYNC/PWM0, TCAP, V1+, V1_sense, V2+, V2_sense, VAUXS

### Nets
3.3VA: C40.1 C41.1 R38.2 U7.37(V33A)
3.3VD: C33.1 C42.1 C43.1 C44.1 C45.1 C51.2 J7.2 R34.1 R38.1 R45.2 R48.2 R56.2 R57.2 TP16.1 U5.2(OUTPUT) U5.4(OUTPUT) U7.27(V33D)
12V: C32.1 C37.1 D9.1(K1) R35.1 R49.1 R50.1 TP17.1 U5.3(IN)
AGND: C11.2 C12.2 C25.2 C33.2 C40.2 C41.2 C42.2 C43.2 C44.2 C45.2 C47.2 C52.2 C53.2 C54.2 C55.2 C56.2 C57.2 C59.2 C60.2 C66.2 D10.2(K) J5.1 J6.6 NT1.2 R9.1 R10.1 S1.5(COM) S2.1 S3.1 S4.1 TP19.1 U7.1(AGND) U7.6(DGND) U7.25(FAULT2) U7.26(DGND) U7.29(AGND) U7.30(AGND) U7.32(EAN0) U7.34(EAN1) U7.36(AGND) U7.41(PAD) U7.A1(ANCHOR) U7.A2(ANCHOR) U7.A3(ANCHOR) U7.A4(ANCHOR)
PGND: C32.2 C35.2 C37.2 C48.2 C49.2 C50.2 NT1.1 Q6.2(E) Q7.2(E) R42.1 R43.2 R44.2 R54.1 R55.1 T1.3 U5.1(GND) U6.5(GND)
SGND: C31.2 C34.2 R58.1 R59.1 T1.7 T1.8
6V: C34.1 D8.1(K) R59.2 ; port 6V
CBC1: U7.4(AD04) ; port CBC1
CBC2: U7.3(AD06) ; port CBC2
CHARGE_V1: R52.1 U7.17(DPWM3A) ; port CHARGE_V1
CHARGE_V2: R53.1 U7.18(DPWM3B) ; port CHARGE_V2
DIRECTION: C60.1 R48.1 R51.2 U7.22(TDO/SCI_TX0/PMBUS_ALERT/FAULT0) ; port DIRECTION
DPWM0A: U7.11(DPWM0A) ; port DPWM0A
DPWM0B: U7.12(DPWM0B) ; port DPWM0B
DPWM1A: U7.13(DPWM1A) ; port DPWM1A
DPWM1B: U7.14(DPWM1B) ; port DPWM1B
DPWM2A: J5.3 U7.15(DPWM2A) ; port DPWM2A
I_Share: C47.1 R40.1 U7.40(AD02) ; port I_Share
Iout1: U7.38(AD00) ; port Iout1
Iout2: U7.2(AD13) ; port Iout2
Iout2_sense: U7.33(EAP1) ; port Iout2_sense
PMBUS_CLK: C59.1 R47.2 U7.9(PMBUS_CLK/SCI_TX0) ; port PMBUS_CLK
PMBUS_DATA: C55.1 R46.2 U7.10(PMBUS_DATA/SCI_RX0) ; port PMBUS_DATA
SYNC/PWM0: J5.4 U7.21(TCK/TCAP/SYNC/PWM0) ; port SYNC/PWM0
TCAP: J5.5 U7.8(ADC_EXT_TRIG/TCAP/SYNC/PWM0) ; port TCAP
V1+: D5.2(A) R1.2 ; port V1+
V1_sense: C11.1 C66.1 R1.1 R9.2 U7.5(AD03) U7.35(EAP2) ; port V1_sense
V2+: D7.2(A) R2.2 ; port V2+
V2_sense: C12.1 C25.1 R2.1 R10.2 U7.31(EAP0) U7.39(AD01) ; port V2_sense
VAUXS: C31.1 D6.3(K) R58.2 ; port VAUXS
NetC35_1: C35.1 D5.1(K) D7.1(K) R33.1 T1.4
NetC36_1: C36.1 R35.2 R42.2 U6.2(FB)
NetC36_2: C36.2 C39.1 R36.1
NetC38_1: C38.1 Q5.5(D) Q5.6(D) Q5.7(D) Q5.8(D) T1.1
NetC38_2: C38.2 R39.1
NetC39_2: C39.2 R36.2 U6.1(COMP)
NetC46_1: C46.1 R43.1
NetC46_2: C46.2 R37.2 U6.4(RC)
NetC48_1: C48.1 R37.1 U6.8(REF)
NetC49_1: C49.1 R41.2 U6.3(CS)
NetC50_1: C50.1 D9.2(K2) R33.2 U6.7(VCC)
NetC51_1: C51.1 C52.1 C53.1 U7.28(BP18)
NetC54_1: C54.1 R45.1 S2.2 U7.7(~{RESET})
NetC56_1: C56.1 R56.1 S3.2 U7.23(TDI/SCI_RX0/PMBUS_CTRL/FAULT1)
NetC57_1: C57.1 R57.1 S4.2 U7.24(TMS)
NetD6_1: D6.1(A) T1.5
NetD8_2: D8.2(A) T1.6
NetD9_3: D9.3(A) T1.2
NetD10_1: D10.1(A) R34.2
NetD11_1: D11.1(A) R49.2
NetD11_2: D11.2(K) Q6.3(C)
NetD12_1: D12.1(A) R50.2
NetD12_2: D12.2(K) Q7.3(C)
NetJ5_2: J5.2 R40.2
NetJ6_5: J6.5 J7.1
NetJ6_9: J6.9 R47.1
NetJ6_10: J6.10 R46.1
NetQ5_1: Q5.1(S) Q5.2(S) Q5.3(S) R39.2 R41.1 R44.1
NetQ5_4: Q5.4(G) U6.6(OUT)
NetQ6_1: Q6.1(B) R52.2 R54.2
NetQ7_1: Q7.1(B) R53.2 R55.2
NetR51_1: R51.1 S1.6

Not connected (* = marked no-connect by the designer): J6 1 2 3 4 7 8; S1 4; U7 16(DPWM2B) 19(PMBUS_ALERT) 20(PMBUS_CTRL)

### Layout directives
net class HV: NetC35_1, NetC38_1

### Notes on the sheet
- 21V at Vin=75

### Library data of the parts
C11 C12 = CMP-0007427-4: CAP, CERM, 6800 pF, 25 V, +/- 10%, X7R, 0603; Manufacturer: MuRata; TaMin_C: -55°C; Polarized: N; SizeAreaWB_mm2: 4.68; Value1: Unknown; U/M: EA; Value: 6800pF; TaMax_C: 125°C; SizeZ_mm: 1; SizeX_mm: 1.6; SizeY_mm: 0.8; Value2: 25V; SizeArea_mm2: 1.28; Cap_F: 6.8nF; AEC Category: Q200
C25 C66 = CMP-0006895-4: CAP, CERM, 220 pF, 50 V, +/- 10%, X7R, 0603; Manufacturer: Kemet; TaMin_C: -55°C; Polarized: N; SizeAreaWB_mm2: 4.68; Value1: Unknown; U/M: EA; Value: 220pF; TaMax_C: 125°C; SizeZ_mm: 1; SizeX_mm: 1.6; SizeY_mm: 0.8; Value2: 50V; SizeArea_mm2: 1.28; AEC Category: Q200
C31 C34 = CMP-0007770-2: CAP, CERM, 2.2 uF, 16 V, +/- 10%, X7R, 0805; PartNumber: C0805C225K4RACTU; Manufacturer: Kemet; Value: 2.2uF; Polarized: N; U/M: EA; Cap_F: 2.2µF; ESR_ohm: 8m; Value1: 0.008 ohm; VDC_V: 16V; IRMS_A: 15.55A; TaMin_C: -55°C; TaMax_C: 125°C; Cap_Case: 0805; AEC Category: Q200; SizeArea_mm2: 2.5; SizeAreaWB_mm2: 6.75; SizeX_mm: 2; SizeY_mm: 1.25; SizeZ_mm: 1.45
C32 = CMP-0007828-2: CAP, CERM, 10 uF, 25 V, +/- 10%, X5R, 0805; PartNumber: C2012X5R1E106K125AB; Manufacturer: TDK; Polarized: N; Value: 10uF; U/M: EA; Cap_F: 10µF; Value1: Unknown; VDC_V: 25V; TaMin_C: -55°C; TaMax_C: 85°C; Cap_Case: 0805; AEC Category: Q200; SizeArea_mm2: 2.5; SizeAreaWB_mm2: 6.75; SizeX_mm: 2; SizeY_mm: 1.25; SizeZ_mm: 1.45
C33 = CMP-0006872-5: CAP, CERM, 10 uF, 6.3 V, +/- 20%, X5R, 0603; PartNumber: C0603C106M9PACTU; Manufacturer: Kemet; Polarized: N; Value: 10uF; U/M: EA; Cap_F: 10µF; ESR_ohm: 4m; Value1: 0.004 ohm; VDC_V: 6.3V; IRMS_A: 8.9A; TaMin_C: -55°C; TaMax_C: 85°C; AEC Category: Q200; SizeArea_mm2: 1.28; SizeAreaWB_mm2: 4.68; SizeX_mm: 1.6; SizeY_mm: 0.8; SizeZ_mm: 1
C35 = CMP-0009232-2: CAP, CERM, 2.2 uF, 100 V, +/- 10%, X7R, 1210; Manufacturer: MuRata; TaMin_C: -55°C; ESR_ohm: 7m; Polarized: N; SizeAreaWB_mm2: 14.7; Value1: 0.007 ohm; U/M: EA; Value: 2.2uF; TaMax_C: 125°C; SizeZ_mm: 2.7; SizeX_mm: 3.2; SizeY_mm: 2.5; Cap_Case: 1210; Value2: 100V; SizeArea_mm2: 8; CompType: Capacitor; Cap_F: 2.2µF; IRMS_A: 4.4A; AEC Category: Q200
C36 = CMP-0006854-4: CAP, CERM, 0.01 uF, 50 V, +/- 10%, X7R, 0603; PartNumber: C0603C103K5RACTU; Manufacturer: Kemet; Value: 0.01uF; Polarized: N; U/M: EA; Cap_F: 10nF; Value1: Unknown; VDC_V: 50V; TaMin_C: -55°C; TaMax_C: 125°C; AEC Category: Q200; SizeArea_mm2: 1.28; SizeAreaWB_mm2: 4.68; SizeX_mm: 1.6; SizeY_mm: 0.8; SizeZ_mm: 1
C37 = CMP-0007120-4: CAP, CERM, 1 uF, 16 V, +/- 10%, X7R, 0603; Manufacturer: Taiyo Yuden; TaMin_C: -55°C; Polarized: N; SizeAreaWB_mm2: 4.68; Value1: Unknown; U/M: EA; Value: 1uF; TaMax_C: 85°C; SizeZ_mm: 1; SizeX_mm: 1.6; SizeY_mm: 0.8; Value2: 16V; SizeArea_mm2: 1.28; CompType: Capacitor; Cap_F: 1µF; AEC Category: Q200
C38 = CMP-0008244-2: CAP, CERM, 47 pF, 250 V, +/- 5%, C0G/NP0, 0805; PartNumber: GRM21A5C2E470JW01D; Manufacturer: MuRata; Value: 47pF; Polarized: N; U/M: EA; Value1: Unknown; VDC_V: 250V; TaMin_C: -55°C; TaMax_C: 125°C; Cap_Case: 0805; AEC Category: Q200; SizeArea_mm2: 2.5; SizeAreaWB_mm2: 6.75; SizeX_mm: 2; SizeY_mm: 1.25; SizeZ_mm: 1.45
C39 = CMP-0006789-4: CAP, CERM, 47 pF, 50 V, +/- 5%, C0G/NP0, 0603; PartNumber: 06035A470JAT2A; Manufacturer: AVX; Value: 47pF; Polarized: N; U/M: EA; ESR_ohm: 1.74d; Value1: 0.174 ohm; VDC_V: 50V; TaMin_C: -55°C; TaMax_C: 125°C; AEC Category: Q200; SizeArea_mm2: 1.28; SizeAreaWB_mm2: 4.68; SizeX_mm: 1.6; SizeY_mm: 0.8; SizeZ_mm: 1
C40 C47 C60 = CMP-0006726-4: as C26 on sheet PMP21529_Sheet1
C41 = CMP-0006868-5: CAP, CERM, 1 uF, 16 V, +/- 10%, X5R, 0603; PartNumber: C0603C105K4PACTU; Manufacturer: Kemet; Polarized: N; Value: 1uF; U/M: EA; Cap_F: 1µF; Value1: Unknown; VDC_V: 16V; TaMin_C: -55°C; TaMax_C: 85°C; AEC Category: Q200; SizeArea_mm2: 1.28; SizeAreaWB_mm2: 4.68; SizeX_mm: 1.6; SizeY_mm: 0.8; SizeZ_mm: 1
C42-C44 = CMP-0006659-2: CAP, CERM, 0.1 uF, 25 V, +/- 10%, X7R, 0402; Manufacturer: MuRata; TaMin_C: -55°C; Polarized: N; SizeAreaWB_mm2: 3; Value1: Unknown; U/M: EA; Value: 0.1uF; TaMax_C: 125°C; SizeZ_mm: 0.6; SizeX_mm: 1; SizeY_mm: 0.5; Value2: 25V; Cap_F: 100nF; AEC Category: Q200
C45 = CMP-0064947-2: CAP, CERM, 1 uF, 6.3 V,+/- 10%, X7R, 0402; Manufacturer: MuRata; TaMin_C: -55°C; Polarized: N; SizeAreaWB_mm2: 3; Value1: Unknown; U/M: EA; Value: 1uF; TaMax_C: 125°C; SizeZ_mm: 0.6; SizeX_mm: 1; SizeY_mm: 0.5; Value2: 6.3V; Cap_F: 1µF; AEC Category: Q200
C46 = CMP-0006921-4: CAP, CERM, 330 pF, 50 V, +/- 10%, X7R, 0603; PartNumber: C0603C331K5RACTU; Manufacturer: Kemet; Value: 330pF; Polarized: N; U/M: EA; Value1: Unknown; VDC_V: 50V; TaMin_C: -55°C; TaMax_C: 125°C; AEC Category: Q200; SizeArea_mm2: 1.28; SizeAreaWB_mm2: 4.68; SizeX_mm: 1.6; SizeY_mm: 0.8; SizeZ_mm: 1
C48 = CMP-0006802-4: CAP, CERM, 0.1 uF, 50 V, +/- 10%, X7R, 0603; PartNumber: 06035C104KAT2A; Manufacturer: AVX; Value: 0.1uF; Polarized: N; U/M: EA; Cap_F: 100nF; Value1: Unknown; VDC_V: 50V; TaMin_C: -55°C; TaMax_C: 125°C; AEC Category: Q200; SizeArea_mm2: 1.28; SizeAreaWB_mm2: 4.68; SizeX_mm: 1.6; SizeY_mm: 0.8; SizeZ_mm: 1
C49 = CMP-0006895-4: CAP, CERM, 220 pF, 50 V, +/- 10%, X7R, 0603; PartNumber: C0603C221K5RACTU; Manufacturer: Kemet; Value: 220pF; Polarized: N; U/M: EA; Value1: Unknown; VDC_V: 50V; TaMin_C: -55°C; TaMax_C: 125°C; AEC Category: Q200; SizeArea_mm2: 1.28; SizeAreaWB_mm2: 4.68; SizeX_mm: 1.6; SizeY_mm: 0.8; SizeZ_mm: 1
C50 = CMP-0008334-2: CAP, CERM, 4.7 uF, 16 V, +/- 10%, X7R, 0805; PartNumber: GRM21BR71C475KA73L; Manufacturer: MuRata; Value: 4.7uF; Polarized: N; U/M: EA; Cap_F: 4.7µF; ESR_ohm: 6m; Value1: 0.006 ohm; VDC_V: 16V; TaMin_C: -55°C; TaMax_C: 125°C; Cap_Case: 0805; AEC Category: Q200; SizeArea_mm2: 2.5; SizeAreaWB_mm2: 6.75; SizeX_mm: 2; SizeY_mm: 1.25; SizeZ_mm: 1.45
C51 = CMP-0006906-5: as C20 on sheet PMP21529_Sheet1
C52 = CMP-0007120-4: CAP, CERM, 1 uF, 16 V, +/- 10%, X7R, 0603; Manufacturer: Taiyo Yuden; TaMin_C: -55°C; Polarized: N; SizeAreaWB_mm2: 4.68; Value1: Unknown; U/M: EA; Value: 1uF; TaMax_C: 85°C; SizeZ_mm: 1; SizeX_mm: 1.6; SizeY_mm: 0.8; Value2: 16V; SizeArea_mm2: 1.28; Cap_F: 1µF; AEC Category: Q200
C53 = CMP-0006975-4: CAP, CERM, 0.01 uF, 25 V, +/- 5%, C0G/NP0, 0603; Manufacturer: Kemet; TaMin_C: -55°C; Polarized: N; SizeAreaWB_mm2: 4.68; Value1: Unknown; U/M: EA; Value: 0.01uF; TaMax_C: 200°C; SizeZ_mm: 1; SizeX_mm: 1.6; SizeY_mm: 0.8; Value2: 25V; SizeArea_mm2: 1.28; Cap_F: 10nF; AEC Category: Q200
C54 C56 C57 = CMP-0064934-4: CAP, CERM, 2.2 uF, 16 V,+/- 10%, X7R, 0603; Manufacturer: Taiyo Yuden; TaMin_C: -55°C; Polarized: N; SizeAreaWB_mm2: 4.68; Value1: Unknown; U/M: EA; Value: 2.2uF; TaMax_C: 125°C; SizeZ_mm: 1; SizeX_mm: 1.6; SizeY_mm: 0.8; Value2: 16V; SizeArea_mm2: 1.28; Cap_F: 2.2µF; AEC Category: Q200
C55 C59 = CMP-0006722-4: CAP, CERM, 33 pF, 100 V, +/- 5%, C0G/NP0, 0603; PartNumber: 06031A330JAT2A; Manufacturer: AVX; Polarized: N; Value: 33pF; U/M: EA; ESR_ohm: 2.09d; Value1: 0.209 ohm; VDC_V: 100V; TaMin_C: -55°C; TaMax_C: 125°C; AEC Category: Q200; SizeArea_mm2: 1.28; SizeAreaWB_mm2: 4.68; SizeX_mm: 1.6; SizeY_mm: 0.8; SizeZ_mm: 1
D5 D7 = CMP-0028782-1: Diode, Schottky, 100 V, 1 A, AEC-Q101, SOD-123W; Manufacturer: Nexperia; Io_A: 1A; Green_Lifecycle: Not Set; SizeAreaWB_mm2: 12.15; Vr_V: 100V; Green_REACh: Incomplete; TJmax_C: 175°C; U/M: EA; Value: 100V; SizeZ_mm: 1; SizeX_mm: 3.5; SizeY_mm: 1.7; Vf_V: 7.7dV; Value2: 0.77V; SizeArea_mm2: 5.95; AEC Qualified: Y; AEC Category: Q101
D6 = CMP-0076887-1: Diode, P-N, 100 V, 0.2 A, SOT-23; PartNumber: MMBD914; Manufacturer: Fairchild Semiconductor; Value: 100V; U/M: EA; Vf_V: 9.5dV; Value1: 0.2A; Value2: 0.95V; Io_A: 2dA; TJmax_C: 150°C; AEC Category: Q101; Green_Lifecycle: Active; Green_REACh: Passed; SizeArea_mm2: 7.5; SizeAreaWB_mm2: 14.0; SizeX_mm: 2.5; SizeY_mm: 3.0; SizeZ_mm: 1.1
D8 = CMP-0028548-1: Diode, Schottky, 40 V, 1 A, SOD-123FL; Manufacturer: ON Semiconductor; Io_A: 1A; Green_Lifecycle: Active; SizeAreaWB_mm2: 12.19; Vr_V: 40V; Green_REACh: Passed; TJmax_C: 125°C; U/M: EA; Value: 40V; SizeZ_mm: 0.98; SizeX_mm: 3.6; SizeY_mm: 1.65; Vf_V: 5.5dV; Value2: 0.55V; SizeArea_mm2: 5.94; AEC Category: Q101; RJC_CperW: 26
D9 = CMP-0076885-1: Diode, Switching, 70 V, 0.25 A, SOT-23; PartNumber: BAW56-V-GS08; Manufacturer: Vishay-Semiconductor; Value: 70V; U/M: EA; Vf_V: 0V; Value1: 0.25A; Io_A: 2.5dA; TJmax_C: 150°C; AEC Category: Q101; Green_Lifecycle: Not Set; Green_REACh: Incomplete; SizeArea_mm2: 7.5; SizeAreaWB_mm2: 14.0; SizeX_mm: 2.5; SizeY_mm: 3.0; SizeZ_mm: 1.1
D10-D12 = CMP-0002827-2: LED, Green, SMD; Manufacturer: Lite-On; Io_A: 20mA; Power_TotalModule: 100mW; Value1: 0.1W; U/M: EA; Vf_V: 2.1V
J5 = CMP-0075485-1: Header, 100mil, 5x1, Gold, TH; Manufacturer: Samtec; Green_REACh: Passed; CT: False; Green_Lifecycle: Active; CNHeader: True
J6 = CMP-0054834-2: Header (shrouded), 100mil, 5x2, Gold, TH; PartNumber: 5103308-1; Manufacturer: TE Connectivity; Green_Lifecycle: Active; Green_REACh: Passed
J7 = CMP-0075626-1: Header, 100mil, 2x1, Gold, TH; Manufacturer: Samtec; Pitch_mm: 2.54; Gender: Male; Cert_CSA: Y; CT: False; Row_Count: 1
NT1 = CMP-0078142-1: Single point connection between nets.
Q5 = CMP-0001082-1: MOSFET, N-CH, 200 V, 3 A, SOIC-8; Alternate Manufacturer: None; Manufacturer: Fairchild Semiconductor; SizeZ_mm: 1.75; ChType: N; Value2: 27 nC; VdsMax_V: 200V; SizeX_mm: 5.99; SizeY_mm: 4.9; Vgs_V: 20V; Value: 200V; SizeArea_mm2: 29.351; AEC Category: Q101; IdsMax_A: 3A; SizeAreaWB_mm2: 55.131; U/M: EA; QgTyp_nC: 27
Q6 Q7 = CMP-0000386-2: Transistor, NPN, 40 V, 0.2 A, SOT-23; Manufacturer: Fairchild Semiconductor; TaMax_C: 150°C; Value2: 300; Value1: 0.2 A; Vcesat1_V: 2dV; SizeX_mm: 2.5; SizeY_mm: 3; TaMin_C: -55°C; IcRated_A: 2dA; CompType: BJT; SizeZ_mm: 1.1; Value: 40 V; SizeArea_mm2: 7.5; NPN: 1; Vceo_V: 40V; PNP: 0; AEC Category: Q101; SizeAreaWB_mm2: 14; U/M: EA
R1 R2 = CMP-0024222-3: RES, 41.2 k, 0.1%, 0.1 W, 0603; Manufacturer: Yageo America; Power_W: 100mW; TempCo: 25 ppm/C; Value_Code: 41k2; U/M: EA; Value: 41.2k; EIA_Code: E192; SizeX_mm: 1.6; SizeY_mm: 0.8; SizeZ_mm: 1; Value2: 0.1W; SizeArea_mm2: 1.28; VDC_V: 75V; AEC Category: Q200
R9 R10 = CMP-0023875-3: RES, 1.10 k, 0.1%, 0.1 W, 0603; Manufacturer: Yageo America; Power_W: 100mW; TempCo: 25 ppm/C; Value_Code: 1k10; U/M: EA; Value: 1.10k; EIA_Code: E192; Res_ohm: 1.1k; SizeX_mm: 1.6; SizeY_mm: 0.8; SizeZ_mm: 1; Value2: 0.1W; SizeArea_mm2: 1.28; VDC_V: 75V; AEC Category: Q200
R33 = CMP-0021486-3: RES, 90.9 k, 1%, 0.125 W, AEC-Q200 Grade 0, 0805; PartNumber: CRCW080590K9FKEA; Manufacturer: Vishay-Dale; Value_Code: 90k9; Power_W: 125mW; Value2: 0.125W; VDC_V: 150V; TempCo: 100 ppm/C; EIA_Code: E96; AEC Category: Q200; AEC Grade: 0; AEC Qualified: Y; SizeArea_mm2: 2.5; SizeX_mm: 2; SizeY_mm: 1.25; SizeZ_mm: 1.45
R34 R49 R50 = CMP-0022109-5: RES, 1.00 k, 1%, 0.1 W, AEC-Q200 Grade 0, 0603; PartNumber: CRCW06031K00FKEA; Manufacturer: Vishay-Dale; Res_ohm: 1k; Value_Code: 1k00; Power_W: 100mW; Value2: 0.1W; VDC_V: 75V; TempCo: 100 ppm/C; EIA_Code: E96; AEC Category: Q200; AEC Grade: 0; AEC Qualified: Y; SizeArea_mm2: 1.28; SizeX_mm: 1.6; SizeY_mm: 0.8; SizeZ_mm: 1
R35 = CMP-0022066-4: RES, 15.0 k, 1%, 0.1 W, AEC-Q200 Grade 0, 0603; PartNumber: CRCW060315K0FKEA; Manufacturer: Vishay-Dale; Value: 15.0k; Res_ohm: 15k; Value_Code: 15k0; Power_W: 100mW; Value2: 0.1W; VDC_V: 75V; TempCo: 100 ppm/C; EIA_Code: E96; AEC Category: Q200; AEC Grade: 0; AEC Qualified: Y; SizeArea_mm2: 1.28; SizeX_mm: 1.6; SizeY_mm: 0.8; SizeZ_mm: 1
R36 R37 = CMP-0022220-4: RES, 22.1 k, 1%, 0.1 W, AEC-Q200 Grade 0, 0603; PartNumber: CRCW060322K1FKEA; Manufacturer: Vishay-Dale; Value: 22.1k; Value_Code: 22k1; Power_W: 100mW; Value2: 0.1W; VDC_V: 75V; TempCo: 100 ppm/C; EIA_Code: E96; AEC Category: Q200; AEC Grade: 0; AEC Qualified: Y; SizeArea_mm2: 1.28; SizeX_mm: 1.6; SizeY_mm: 0.8; SizeZ_mm: 1
R38 = CMP-0024910-2: RES, 1.00, 0.5%, 0.1 W, 0603; Manufacturer: Yageo America; Power_W: 100mW; TempCo: 50 ppm/C; Value_Code: 1R00; U/M: EA; Value: 1.00; EIA_Code: E192; Res_ohm: 1; SizeX_mm: 1.6; SizeY_mm: 0.8; Value2: 0.1W; SizeArea_mm2: 1.28; VDC_V: 75V; AEC Category: Q200
R39 = CMP-0022588-5: RES, 750, 1%, 0.1 W, AEC-Q200 Grade 0, 0603; PartNumber: CRCW0603750RFKEA; Manufacturer: Vishay-Dale; Value: 750; Value_Code: 750R; Power_W: 100mW; Value2: 0.1W; VDC_V: 75V; TempCo: 100 ppm/C; EIA_Code: E96; AEC Category: Q200; AEC Grade: 0; AEC Qualified: Y; SizeArea_mm2: 1.28; SizeX_mm: 1.6; SizeY_mm: 0.8; SizeZ_mm: 1
R40 R46 R47 R51 = CMP-0021991-4: RES, 100, 1%, 0.1 W, AEC-Q200 Grade 0, 0603; PartNumber: CRCW0603100RFKEA; Manufacturer: Vishay-Dale; Value_Code: 100R; Power_W: 100mW; Value2: 0.1W; VDC_V: 75V; TempCo: 100 ppm/C; EIA_Code: E96; AEC Category: Q200; AEC Grade: 0; AEC Qualified: Y; SizeArea_mm2: 1.28; SizeX_mm: 1.6; SizeY_mm: 0.8; SizeZ_mm: 1
R41 = CMP-0022109-5: RES, 1.00 k, 1%, 0.1 W, AEC-Q200 Grade 0, 0603; PartNumber: CRCW06031K00FKEA; Manufacturer: Vishay-Dale; Value: 1.00k; Res_ohm: 1k; Value_Code: 1k00; Power_W: 100mW; Value2: 0.1W; VDC_V: 75V; TempCo: 100 ppm/C; EIA_Code: E96; AEC Category: Q200; AEC Grade: 0; AEC Qualified: Y; SizeArea_mm2: 1.28; SizeX_mm: 1.6; SizeY_mm: 0.8; SizeZ_mm: 1
R42 = CMP-0022454-4: RES, 4.53 k, 1%, 0.1 W, AEC-Q200 Grade 0, 0603; Manufacturer: Vishay-Dale; Power_W: 100mW; TempCo: 100 ppm/C; Value_Code: 4k53; Value: 4.53k; EIA_Code: E96; SizeX_mm: 1.6; SizeY_mm: 0.8; SizeZ_mm: 1; Value2: 0.1W; SizeArea_mm2: 1.28; AEC Qualified: Y; VDC_V: 75V; AEC Category: Q200; AEC Grade: 0
R43 = CMP-0022341-4: RES, 33.2, 1%, 0.1 W, AEC-Q200 Grade 0, 0603; PartNumber: CRCW060333R2FKEA; Manufacturer: Vishay-Dale; Value: 33.2; Value_Code: 33R2; Power_W: 100mW; Value2: 0.1W; VDC_V: 75V; TempCo: 100 ppm/C; EIA_Code: E96; AEC Category: Q200; AEC Grade: 0; AEC Qualified: Y; SizeArea_mm2: 1.28; SizeX_mm: 1.6; SizeY_mm: 0.8; SizeZ_mm: 1
R44 = CMP-0021231-3: RES, 3.01, 1%, 0.125 W, AEC-Q200 Grade 0, 0805; PartNumber: CRCW08053R01FKEA; Manufacturer: Vishay-Dale; Value_Code: 3R01; Power_W: 125mW; Value2: 0.125W; VDC_V: 150V; TempCo: 100 ppm/C; EIA_Code: E96; AEC Category: Q200; AEC Grade: 0; AEC Qualified: Y; SizeArea_mm2: 2.5; SizeX_mm: 2; SizeY_mm: 1.25; SizeZ_mm: 1.45
R45 R56 R57 = CMP-0025769-4: RES, 2.2 k, 5%, 0.1 W, AEC-Q200 Grade 0, 0603; Manufacturer: Vishay-Dale; Power_W: 100mW; TempCo: 200 ppm/C; Value_Code: 2k20; Value: 2.2k; EIA_Code: E24; SizeX_mm: 1.6; SizeY_mm: 0.8; SizeZ_mm: 1; Value2: 0.1W; SizeArea_mm2: 1.28; AEC Qualified: Y; VDC_V: 75V; AEC Category: Q200; AEC Grade: 0
R48 R54 R55 = CMP-0021998-4: as R3 on sheet PMP21529_Sheet1
R52 R53 = CMP-0022373-4: RES, 3.16 k, 1%, 0.1 W, AEC-Q200 Grade 0, 0603; Manufacturer: Vishay-Dale; Power_W: 100mW; TempCo: 100 ppm/C; Value_Code: 3k16; Value: 3.16k; EIA_Code: E96; SizeX_mm: 1.6; SizeY_mm: 0.8; SizeZ_mm: 1; Value2: 0.1W; SizeArea_mm2: 1.28; AEC Qualified: Y; VDC_V: 75V; AEC Category: Q200; AEC Grade: 0
R58 R59 = CMP-0025750-4: RES, 200 k, 5%, 0.1 W, AEC-Q200 Grade 0, 0603; Manufacturer: Vishay-Dale; Power_W: 100mW; TempCo: 200 ppm/C; Value: 200k; EIA_Code: E24; SizeX_mm: 1.6; SizeY_mm: 0.8; SizeZ_mm: 1; Value2: 0.1W; SizeArea_mm2: 1.28; AEC Qualified: Y; VDC_V: 75V; AEC Category: Q200; AEC Grade: 0
S1 = CMP-0002136-2: Switch, Toggle, SPDT 1Pos, TH; Manufacturer: NKK Switches; CurrentRating_mA: 400A; PositionCount: 1; VDC_V: 28V; SwitchFunction: On-On
S2-S4 = CMP-0002113-2: Switch, Push Button, SMD; Manufacturer: Alps; CurrentRating_mA: 50A; SwitchFunction: Off-Mom; Circuit: SPST-NO; VDC_V: 12V; PositionCount: 1
T1 = CMP-0030144-1: Auxiliary Flyback Transformer, 540 uH, SMT; Manufacturer: XFMRS, Inc.; DCR_ohm: 3.5; Value: 540uH; Lp: 540; Ind_H: 540µH; LeakageInd_H: 25µH
TP16 TP17 = CMP-0055149-1: as TP1 on sheet PMP21529_Sheet1
TP19 = CMP-0055148-1: as TP11 on sheet PMP21529_Sheet1
U5 = CMP-0066030-1: Single-Output LDO, 800mA, Fixed (3.3), Internal Current Limit, Thermal Overload Protection, DCY0004A (SOT-223-4); Alternate Manufacturer: Texas Instruments; Green_Lifecycle: Active; SizeAreaWB_mm2: 76.5; Green_REACh: Passed; U/M: EA; SizeZ_mm: 1.8; SizeX_mm: 7.0; SizeY_mm: 6.5; SizeArea_mm2: 45.5; CompType: IC
U6 = CMP-0067253-1: Low Power Economy BiCMOS Current Mode PWM, D0008A (SOIC-8); Alternate Manufacturer: Texas Instruments; CompType: IC; U/M: EA; Green_Lifecycle: Active; Green_REACh: Passed; SizeArea_mm2: 30.38; SizeAreaWB_mm2: 56.58; SizeX_mm: 4.9; SizeY_mm: 6.2; SizeZ_mm: 1.75
U7 = CMP-0081542-1: Highly Integrated Digital Controller for Isolated Power with 3 Feedback Loops and 8 DPWM Outputs, RJA0040A (VQFN-40); Alternate PartNumber: UCD3138RJAR; Alternate Manufacturer: Texas Instruments; SizeAreaWB_mm2: 64; Rating: Catalog; SizeZ_mm: 1; SizeX_mm: 6; SizeArea_mm2: 36; CompType: IC; AEC Qualified: N; AEC Category: Q200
